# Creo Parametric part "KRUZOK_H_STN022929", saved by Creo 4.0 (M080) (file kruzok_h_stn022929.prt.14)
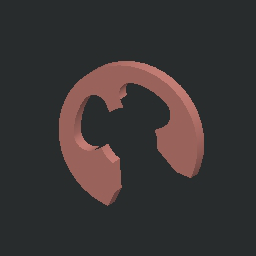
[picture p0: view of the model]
Units: millimeter Newton Second (mmNs); MM, TONNE, SECS
Materials in the file: OCEL_N

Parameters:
  NAZOV = "KRUZOK_H_STN022929"
  NORMA = "STN 02 2929"
  PTC_MATERIAL_NAME = "OCEL_N"

Other parameters: HMOTNOST, HUSTOTA

Created from: C022929.PRT

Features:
  1. datum plane "DTM1"

Layers: ALL_AXIS, ALL_DATUM_PLANES, ALL_THREAD

Family table entries: GENERIC, KRUZOK_H_1D9, KRUZOK_H_STN022929, value(d_val), value(i_val), KRUZOK_H_2D3, KRUZOK_H_STN022929, KRUZOK_H_3D2, KRUZOK_H_STN022929, KRUZOK_H_4, KRUZOK_H_STN022929, 2/", KRUZOK_H_5, KRUZOK_H_STN022929, 2/", 2/&, KRUZOK_H_6, KRUZOK_H_STN022929, 2/#, 2/(, KRUZOK_H_7, KRUZOK_H_STN022929, 2/&, 2/,, KRUZOK_H_9, KRUZOK_H_STN022929, 2/., 2/", KRUZOK_H_12, KRUZOK_H_STN022929, 2/3, 2/7, 2/(, KRUZOK_H_15, KRUZOK_H_STN022929, 2/8, 2/=, 2/., KRUZOK_H_19, KRUZOK_H_STN022929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

Surfaces: 10 plane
